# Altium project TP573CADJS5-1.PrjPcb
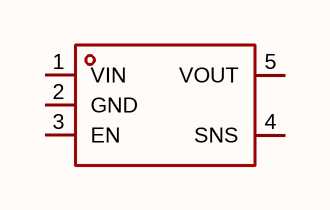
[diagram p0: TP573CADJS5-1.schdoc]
1 sheet, 1 parts. Net scope: global (net labels, ports and power ports of the same name join across sheets).

## Sheet TP573CADJS5-1.schdoc
size 127 x 101 mm

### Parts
Q?  tp573cadjs5-1  [SOT-23-5_L2.9-W1.6-P0.95-LS2.8-BR]  (value not drawn)

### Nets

Not connected (* = marked no-connect by the designer): Q? 1(VIN) 2(GND) 3(EN) 4(SNS) 5(VOUT)

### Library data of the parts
Q? = tp573cadjs5-1: 输出极性:正极;工作电压:50V;输出电压:-;输出电流:200mA;电源纹波抑制比(PSRR):70dB@(100Hz);输出类型:可调;; Manufacturer: TECH PUBLIC(台舟); AddInBom: yes; ModelId: 7ba65df16e7b4570af156e925f9c37fe; ModelTransform: 114.173,114.173,0,90,0,0,0,0,0; Output Configuration: 正极; Voltage - Supply: 50V; Output Current: 200mA; Voltage Dropout: 660mV@(100mA); standby current: 2uA; Output Type: 可调; Number of Outputs: 1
